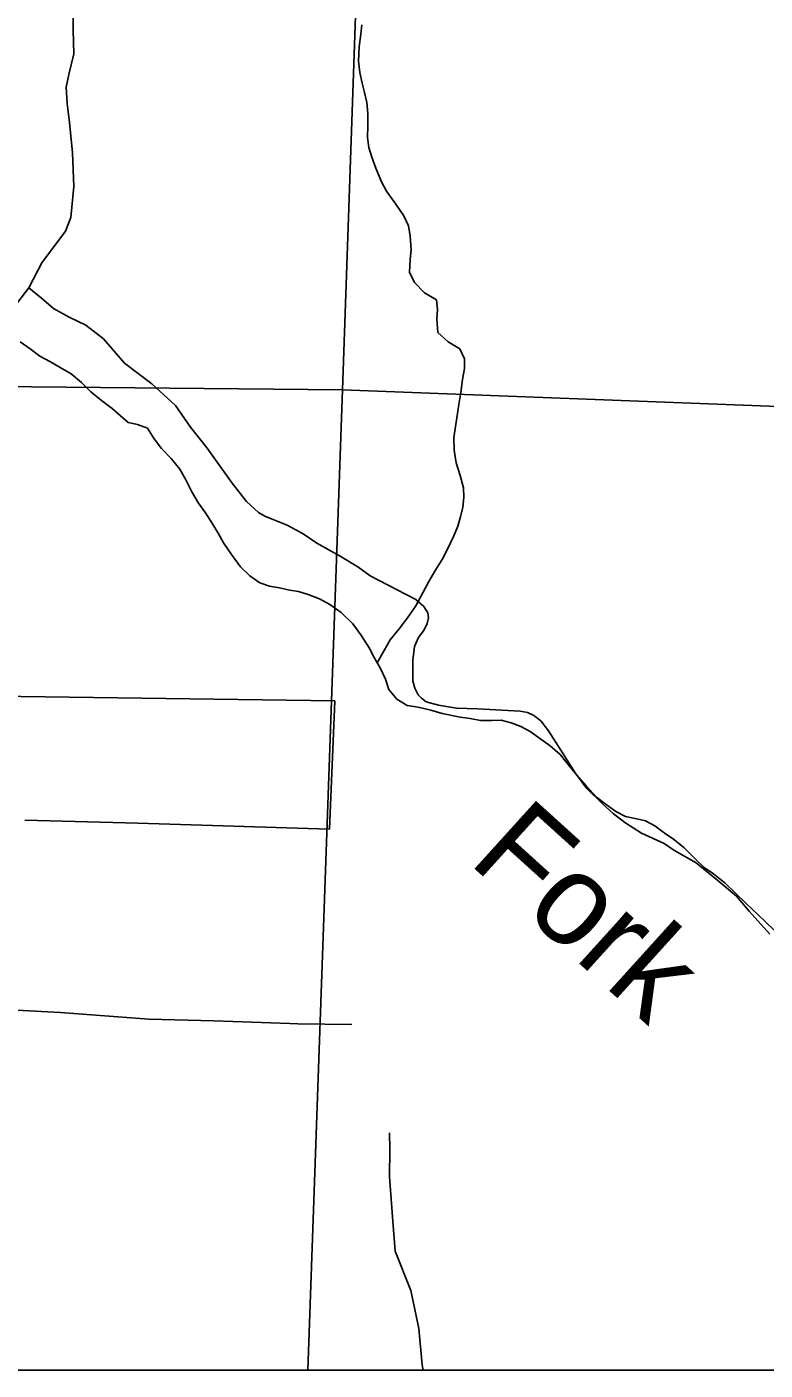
# Model space of a CAD drawing. Extents: x 2.1 to 8.9, y 14.1 to 20.9.
# Drawn here: x 4.099 to 4.863, y 14.1 to 15.488 of the extents above; entities that cross this region are included whole.
import ezdxf

# ---------------------------------------------------------------- set-up
doc = ezdxf.new("R2010")
doc.units = 0
for name, color, linetype in [('Default', 7, 'Continuous'), ('GM_X_City_Street', 7, 'Continuous'), ('GM_X_Interchange_Ramps', 7, 'Continuous'), ('PV_P_Text', 7, 'Continuous'), ('SH_Cut_Line', 7, 'Continuous'), ('SH_Data', 7, 'Continuous'), ('TX_P_Misc', 7, 'Continuous')]:
    doc.layers.add(name, color=color, linetype=linetype)

msp = doc.modelspace()

# ---------------------------------------------------------------- linework, layer by layer
at = {"layer": 'Default'}
for p, q in [((4.4256, 15.1132), (3.4148, 15.1232)), ((4.3897, 14.1), (4.4256, 15.1132)), ((4.4256, 15.1132), (4.3897, 14.1)), ((5.4229, 15.0756), (4.4256, 15.1132)), ((4.4177, 14.7917), (4.023, 14.7972)), ((4.412, 14.6591), (4.4177, 14.7917)), ((4.0972, 14.6685), (4.214, 14.6654)), ((4.214, 14.6654), (4.412, 14.6591)), ((2.1, 14.1), (6.7017, 14.1)), ((3.3681, 14.1), (4.3897, 14.1)), ((4.3897, 14.1), (5.3878, 14.1))]:
    msp.add_line(p, q, dxfattribs=at)
at = {"layer": 'GM_X_City_Street'}
for p, q in [((4.1473, 15.4852), (4.1472, 15.5165)), ((4.1477, 15.4607), (4.1473, 15.4852)), ((4.1428, 15.4394), (4.1477, 15.4607)), ((4.1398, 15.4262), (4.1428, 15.4394)), ((4.1411, 15.4093), (4.1398, 15.4262)), ((4.1433, 15.3896), (4.1411, 15.4093)), ((4.1465, 15.3582), (4.1433, 15.3896)), ((4.1477, 15.3234), (4.1465, 15.3582)), ((4.1447, 15.2915), (4.1477, 15.3234)), ((4.1392, 15.2772), (4.1447, 15.2915)), ((4.1146, 15.2447), (4.1392, 15.2772)), ((4.1013, 15.2188), (4.1146, 15.2447)), ((4.0866, 15.1994), (4.1013, 15.2188)), ((4.1143, 15.2082), (4.1013, 15.2188)), ((4.1267, 15.1972), (4.1143, 15.2082)), ((4.1429, 15.1884), (4.1267, 15.1972)), ((4.1602, 15.1802), (4.1429, 15.1884)), ((4.1784, 15.1659), (4.1602, 15.1802)), ((4.2002, 15.1409), (4.1784, 15.1659)), ((4.2283, 15.1195), (4.2002, 15.1409)), ((4.2529, 15.0972), (4.2283, 15.1195)), ((4.2684, 15.0746), (4.2529, 15.0972)), ((4.2856, 15.053), (4.2684, 15.0746)), ((4.3116, 15.0169), (4.2856, 15.053)), ((4.3262, 14.9977), (4.3116, 15.0169)), ((4.3388, 14.9864), (4.3262, 14.9977)), ((4.3452, 14.9828), (4.3388, 14.9864)), ((4.3529, 14.9796), (4.3452, 14.9828)), ((4.3684, 14.9733), (4.3529, 14.9796)), ((4.3851, 14.9643), (4.3684, 14.9733)), ((4.3991, 14.9547), (4.3851, 14.9643)), ((4.4232, 14.9412), (4.3991, 14.9547)), ((4.4414, 14.9304), (4.4232, 14.9412)), ((4.4543, 14.921), (4.4414, 14.9304)), ((4.4913, 14.9019), (4.4543, 14.921)), ((4.5014, 14.8964), (4.4913, 14.9019)), ((4.5098, 14.8893), (4.5014, 14.8964)), ((4.5139, 14.8828), (4.5098, 14.8893)), ((4.5099, 14.8652), (4.5133, 14.8716)), ((4.5133, 14.8716), (4.5147, 14.8777)), ((4.5147, 14.8777), (4.5139, 14.8828)), ((4.5041, 14.8573), (4.5099, 14.8652)), ((4.4985, 14.8339), (4.4999, 14.8479)), ((4.4999, 14.8479), (4.5041, 14.8573)), ((4.4983, 14.8124), (4.4985, 14.8339)), ((4.5004, 14.805), (4.4983, 14.8124)), ((4.504, 14.798), (4.5004, 14.805)), ((4.5072, 14.7944), (4.504, 14.798)), ((4.512, 14.7909), (4.5072, 14.7944)), ((4.525, 14.7873), (4.512, 14.7909)), ((4.5434, 14.7841), (4.525, 14.7873)), ((4.5652, 14.7834), (4.5434, 14.7841)), ((4.6092, 14.781), (4.5652, 14.7834)), ((4.6168, 14.7799), (4.6092, 14.781)), ((4.6233, 14.7766), (4.6168, 14.7799)), ((4.6307, 14.7712), (4.6233, 14.7766)), ((4.6386, 14.7608), (4.6307, 14.7712)), ((4.6514, 14.7407), (4.6386, 14.7608)), ((4.6662, 14.7174), (4.6514, 14.7407)), ((4.6779, 14.7014), (4.6662, 14.7174)), ((4.6945, 14.6853), (4.6779, 14.7014)), ((4.7055, 14.6755), (4.6945, 14.6853)), ((4.7176, 14.6661), (4.7055, 14.6755)), ((4.7346, 14.6551), (4.7176, 14.6661)), ((4.7583, 14.6445), (4.7346, 14.6551)), ((4.7682, 14.6374), (4.7583, 14.6445)), ((4.7914, 14.6242), (4.7682, 14.6374)), ((4.8118, 14.6073), (4.7914, 14.6242)), ((4.8331, 14.5898), (4.8118, 14.6073)), ((4.846, 14.5744), (4.8331, 14.5898)), ((4.8675, 14.5505), (4.846, 14.5744)), ((4.0884, 14.4719), (4.1342, 14.4695)), ((4.1342, 14.4695), (4.2255, 14.4627)), ((4.2255, 14.4627), (4.2926, 14.4609)), ((4.2926, 14.4609), (4.3711, 14.4582)), ((4.3711, 14.4582), (4.3795, 14.4581)), ((4.3795, 14.4581), (4.4353, 14.4573))]:
    msp.add_line(p, q, dxfattribs=at)
at = {"layer": 'GM_X_Interchange_Ramps'}
for p, q in [((4.4591, 16.088), (4.4256, 15.1132)), ((4.4256, 15.1132), (4.4591, 16.088)), ((4.4256, 15.1132), (3.4148, 15.1232)), ((5.4229, 15.0756), (4.4256, 15.1132))]:
    msp.add_line(p, q, dxfattribs=at)
at = {"layer": 'SH_Cut_Line'}
msp.add_line((2.1, 14.1), (6.7017, 14.1), dxfattribs=at)
at = {"layer": 'SH_Data'}
msp.add_line((2.1, 14.1), (8.9, 14.1), dxfattribs=at)
msp.add_line((2.1, 14.1), (8.9, 14.1), dxfattribs=at)
at = {"layer": 'TX_P_Misc'}
for p, q in [((4.4447, 15.4808), (4.4455, 15.4907)), ((4.4428, 15.4678), (4.4447, 15.4808)), ((4.4421, 15.453), (4.4428, 15.4678)), ((4.4437, 15.4412), (4.4421, 15.453)), ((4.4459, 15.4303), (4.4437, 15.4412)), ((4.4485, 15.4205), (4.4459, 15.4303)), ((4.4507, 15.4103), (4.4485, 15.4205)), ((4.4518, 15.3989), (4.4507, 15.4103)), ((4.4514, 15.3742), (4.4518, 15.3867)), ((4.4518, 15.3867), (4.4518, 15.3989)), ((4.4529, 15.3639), (4.4514, 15.3742)), ((4.4559, 15.3537), (4.4529, 15.3639)), ((4.46, 15.3425), (4.4559, 15.3537)), ((4.4658, 15.3282), (4.46, 15.3425)), ((4.4711, 15.3185), (4.4658, 15.3282)), ((4.4806, 15.3051), (4.4711, 15.3185)), ((4.489, 15.2932), (4.4806, 15.3051)), ((4.4938, 15.2827), (4.489, 15.2932)), ((4.4957, 15.2721), (4.4938, 15.2827)), ((4.4965, 15.258), (4.4957, 15.2721)), ((4.495, 15.2348), (4.4957, 15.2481)), ((4.4957, 15.2481), (4.4965, 15.258)), ((4.5002, 15.2243), (4.495, 15.2348)), ((4.5105, 15.2136), (4.5002, 15.2243)), ((4.5228, 15.2063), (4.5105, 15.2136)), ((4.5239, 15.1965), (4.5228, 15.2063)), ((4.5231, 15.1862), (4.5239, 15.1965)), ((4.5243, 15.1725), (4.5231, 15.1862)), ((4.1028, 15.1557), (4.0923, 15.163)), ((4.5348, 15.163), (4.5243, 15.1725)), ((4.5469, 15.1558), (4.5348, 15.163)), ((4.1126, 15.148), (4.1028, 15.1557)), ((4.5517, 15.1453), (4.5469, 15.1558)), ((4.1238, 15.1423), (4.1126, 15.148)), ((4.1338, 15.1365), (4.1238, 15.1423)), ((4.1451, 15.13), (4.1338, 15.1365)), ((4.5498, 15.1239), (4.5517, 15.1354)), ((4.5517, 15.1354), (4.5517, 15.1453)), ((4.1556, 15.1208), (4.1451, 15.13)), ((4.5479, 15.1105), (4.5498, 15.1239)), ((4.1654, 15.1112), (4.1556, 15.1208)), ((4.1764, 15.1021), (4.1654, 15.1112)), ((4.546, 15.0983), (4.5479, 15.1105)), ((4.1876, 15.094), (4.1764, 15.1021)), ((4.204, 15.0797), (4.1876, 15.094)), ((4.5438, 15.0842), (4.546, 15.0983)), ((4.2136, 15.0773), (4.204, 15.0797)), ((4.5406, 15.0639), (4.5438, 15.0842)), ((4.224, 15.0735), (4.2136, 15.0773)), ((4.2308, 15.0627), (4.224, 15.0735)), ((4.2383, 15.0526), (4.2308, 15.0627)), ((4.2486, 15.0423), (4.2383, 15.0526)), ((4.541, 15.051), (4.5406, 15.0639)), ((4.2573, 15.0312), (4.2486, 15.0423)), ((4.5433, 15.0377), (4.541, 15.051)), ((4.2633, 15.0211), (4.2573, 15.0312)), ((4.5472, 15.0246), (4.5433, 15.0377)), ((4.5506, 15.0121), (4.5472, 15.0246)), ((4.2698, 15.008), (4.2633, 15.0211)), ((4.5509, 15.0019), (4.5506, 15.0121)), ((4.2766, 14.996), (4.2698, 15.008)), ((4.5501, 14.9919), (4.5509, 15.0019)), ((4.2838, 14.9863), (4.2766, 14.996)), ((4.2913, 14.9748), (4.2838, 14.9863)), ((4.5477, 14.982), (4.5501, 14.9919)), ((4.297, 14.9651), (4.2913, 14.9748)), ((4.5407, 14.9624), (4.545, 14.9724)), ((4.545, 14.9724), (4.5477, 14.982)), ((4.3026, 14.955), (4.297, 14.9651)), ((4.311, 14.9431), (4.3026, 14.955)), ((4.5343, 14.9485), (4.5407, 14.9624)), ((4.3201, 14.9304), (4.311, 14.9431)), ((4.5286, 14.938), (4.5343, 14.9485)), ((4.3299, 14.9212), (4.3201, 14.9304)), ((4.521, 14.926), (4.5286, 14.938)), ((4.34, 14.9139), (4.3299, 14.9212)), ((4.35, 14.9104), (4.34, 14.9139)), ((4.5091, 14.9043), (4.5149, 14.9152)), ((4.5149, 14.9152), (4.521, 14.926)), ((4.3603, 14.9085), (4.35, 14.9104)), ((4.3707, 14.9061), (4.3603, 14.9085)), ((4.3802, 14.9049), (4.3707, 14.9061)), ((4.3902, 14.9018), (4.3802, 14.9049)), ((4.4017, 14.8972), (4.3902, 14.9018)), ((4.5016, 14.89), (4.5091, 14.9043)), ((4.4126, 14.8915), (4.4017, 14.8972)), ((4.4242, 14.8831), (4.4126, 14.8915)), ((4.4928, 14.8776), (4.5016, 14.89)), ((4.4364, 14.8713), (4.4242, 14.8831)), ((4.4841, 14.8663), (4.4928, 14.8776)), ((4.4447, 14.8601), (4.4364, 14.8713)), ((4.4531, 14.8467), (4.4447, 14.8601)), ((4.4749, 14.855), (4.4841, 14.8663)), ((4.4584, 14.8366), (4.4531, 14.8467)), ((4.4615, 14.8312), (4.4688, 14.8438)), ((4.4688, 14.8438), (4.4749, 14.855)), ((4.4648, 14.8254), (4.4584, 14.8366)), ((4.4701, 14.8141), (4.4648, 14.8254)), ((4.4735, 14.8036), (4.4701, 14.8141)), ((4.4818, 14.7936), (4.4735, 14.8036)), ((4.4923, 14.7871), (4.4818, 14.7936)), ((4.5037, 14.7851), (4.4923, 14.7871)), ((4.5171, 14.7821), (4.5037, 14.7851)), ((4.5286, 14.7787), (4.5171, 14.7821)), ((4.5474, 14.7751), (4.5286, 14.7787)), ((4.5577, 14.7735), (4.5474, 14.7751)), ((4.5684, 14.7716), (4.5577, 14.7735)), ((4.5802, 14.7715), (4.5684, 14.7716)), ((4.5897, 14.7718), (4.5802, 14.7715)), ((4.6, 14.7691), (4.5897, 14.7718)), ((4.61, 14.7652), (4.6, 14.7691)), ((4.6197, 14.7602), (4.61, 14.7652)), ((4.6306, 14.7522), (4.6197, 14.7602)), ((4.6403, 14.7453), (4.6306, 14.7522)), ((4.6505, 14.7365), (4.6403, 14.7453)), ((4.6588, 14.7261), (4.6505, 14.7365)), ((4.6679, 14.7149), (4.6588, 14.7261)), ((4.6777, 14.7038), (4.6679, 14.7149)), ((4.6883, 14.6924), (4.6777, 14.7038)), ((4.6981, 14.6847), (4.6883, 14.6924)), ((4.7082, 14.6774), (4.6981, 14.6847)), ((4.7182, 14.6724), (4.7082, 14.6774)), ((4.7282, 14.6701), (4.7182, 14.6724)), ((4.7389, 14.6677), (4.7282, 14.6701)), ((4.7486, 14.6627), (4.7389, 14.6677)), ((4.7583, 14.6554), (4.7486, 14.6627)), ((4.768, 14.6489), (4.7583, 14.6554)), ((4.7786, 14.6401), (4.768, 14.6489)), ((4.7899, 14.629), (4.7786, 14.6401)), ((4.7994, 14.6194), (4.7899, 14.629)), ((4.8091, 14.6129), (4.7994, 14.6194)), ((4.8212, 14.6034), (4.8091, 14.6129)), ((4.8321, 14.5931), (4.8212, 14.6034)), ((4.8427, 14.5827), (4.8321, 14.5931)), ((4.8623, 14.564), (4.8427, 14.5827)), ((4.8725, 14.554), (4.8623, 14.564)), ((4.4746, 14.3284), (4.4743, 14.3451)), ((4.4743, 14.2999), (4.4746, 14.3284)), ((4.4778, 14.254), (4.4743, 14.2999)), ((4.4802, 14.2229), (4.4778, 14.254)), ((4.4961, 14.1824), (4.4802, 14.2229)), ((4.5047, 14.1431), (4.4961, 14.1824)), ((4.508, 14.1055), (4.5047, 14.1431)), ((4.509, 14.1), (4.508, 14.1055))]:
    msp.add_line(p, q, dxfattribs=at)

# ---------------------------------------------------------------- texts
at = {"layer": 'PV_P_Text'}
msp.add_text('Fork', height=0.09471, rotation=317.8356, dxfattribs=at).set_placement((4.5544, 14.6252))

doc.saveas('drawing.dxf')
